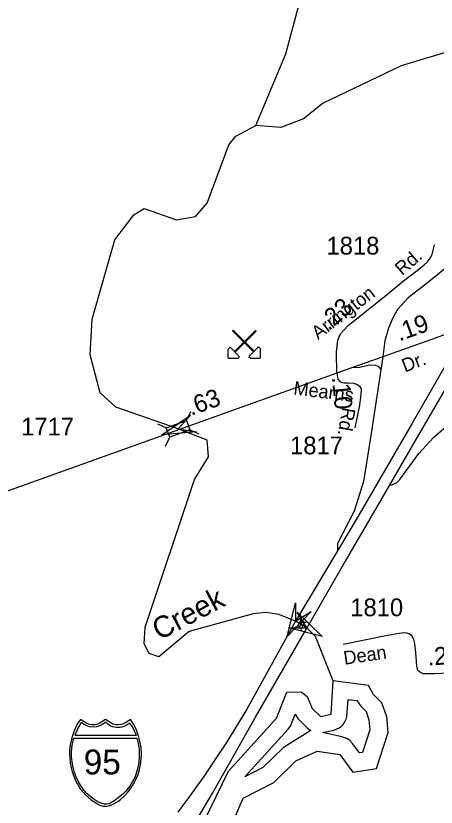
# Model space of a CAD drawing. Extents: x 2220236 to 2384410, y 720751 to 894131.
# Drawn here: x 2314927 to 2317882, y 782328 to 787885 of the extents above; entities that cross this region are included whole.
import ezdxf

# ---------------------------------------------------------------- set-up
doc = ezdxf.new("R2010")
doc.units = 0
for name, color, linetype in [('Exist Geographical Pit Clay CELL', 7, 'Continuous'), ('Exist Hydrographic Buffer Line', 7, 'Continuous'), ('Exist Hydrographic Creek Single Shore', 7, 'Continuous'), ('Exist Hydrographic Creek Single Shore Label', 7, 'Continuous'), ('Exist Hydrographic Lake Shore', 7, 'Continuous'), ('Exist Hydrographic Misc Water Feature', 7, 'Continuous'), ('Exist Road Primary Interstate Divided Center Attributed', 7, 'Continuous'), ('Exist Road Primary Interstate Ramp 1 Lane Attributed', 7, 'Continuous'), ('Exist Road Primary Interstate Shield CELL', 7, 'Continuous'), ('Exist Road Primary Interstate Shield Number Label', 7, 'Continuous'), ('Exist Road Primary Interstate Structure Standard Bridge CELL', 7, 'Continuous'), ('Exist Road Primary US Service Attributed', 7, 'Continuous'), ('Exist Road Secondary Mileage Hundredths English Label', 7, 'Continuous'), ('Exist Road Secondary Structure Standard Bridge Attributed CELL', 7, 'Continuous'), ('Exist Road Secondary Structure Standard Bridge CELL', 7, 'Continuous'), ('Exist Road Secondary Type 51 Attributed', 7, 'Continuous'), ('Exist Road Secondary Type 51 Label', 7, 'Continuous'), ('Exist Road Secondary Type 51 Number Label', 7, 'Continuous')]:
    doc.layers.add(name, color=color, linetype=linetype)

msp = doc.modelspace()

# ---------------------------------------------------------------- linework, layer by layer
at = {"layer": 'Exist Geographical Pit Clay CELL'}
for points in [[(2316597.8, 785524.9), (2316602.6, 785529.7), (2316455.3, 785677), (2316450.5, 785672.2)], [(2316469.6, 785522.4), (2316464.8, 785527.2), (2316612.1, 785674.5), (2316616.9, 785669.7)], [(2316420, 785483), (2316420, 785545.1), (2316433.5, 785558.6), (2316501, 785491.1), (2316487.5, 785477.6), (2316425.4, 785477.6)], [(2316647.4, 785485.4), (2316647.4, 785547.5), (2316633.9, 785561), (2316566.4, 785493.5), (2316579.9, 785480), (2316642, 785480)]]:
    msp.add_lwpolyline(points, close=True, dxfattribs=at)
at = {"layer": 'Exist Hydrographic Buffer Line'}
for points in [[(2317343.6, 782708.6), (2317294, 782774.8), (2317275.1, 782794.8), (2317257.9, 782806.8), (2317238.8, 782815.6), (2317218.7, 782821), (2317082.6, 782851.5), (2317162.2, 782868.6), (2317196.8, 782882), (2317214.2, 782894), (2317229, 782908.8), (2317240.9, 782925.9), (2317249.7, 782944.8), (2317255.2, 782965.1), (2317262.8, 783083.9), (2317323.9, 783076), (2317351.6, 783036.2), (2317389.6, 782999.8), (2317409.7, 782940.7), (2317416.2, 782871.2), (2317365.2, 782712), (2317343.6, 782708.6)], [(2316537.4, 782540.9), (2316842.7, 782876.4), (2316857.9, 782897.2), (2316892.1, 782981.1), (2316911, 782949.3), (2316978.6, 782883.2), (2317001.8, 782865.8), (2316839.8, 782766.5), (2316806.4, 782743.8), (2316663.5, 782605.4), (2316537.4, 782540.9)]]:
    msp.add_lwpolyline(points, dxfattribs=at)
at = {"layer": 'Exist Hydrographic Creek Single Shore'}
for points in [[(2316615.7, 787114.3), (2316826.7, 787618.5), (2316922.7, 787976.9)], [(2317157.7, 783214.5), (2317033.1, 783525.9), (2316974, 783586), (2316932.3, 783611.5), (2316894.3, 783633.8), (2316776.6, 783681.7), (2316688.1, 783693.9), (2316596.5, 783685.8), (2316145.7, 783560.5), (2315931.7, 783384.4), (2315864.6, 783407.9), (2315830.6, 783475.5), (2315837.7, 783590.6), (2316184.7, 784628.7), (2316282.7, 784787), (2316272.7, 784904.8), (2316069.5, 784983.8), (2315629.6, 785137.8), (2315519.7, 785238.2), (2315450.6, 785504.5), (2315464.8, 785754.6), (2315624.7, 786312.5), (2315756.7, 786488.4), (2315830.6, 786530.9), (2316056.7, 786451.5), (2316189.6, 786476.7), (2316271.6, 786568.6), (2316425.6, 786978.5), (2316474.6, 787039.6), (2316615.7, 787114.3)]]:
    msp.add_lwpolyline(points, dxfattribs=at)
at = {"layer": 'Exist Hydrographic Lake Shore'}
for points in [[(2316364.7, 779440.9), (2316363.7, 779598.3), (2316537.6, 780376.7), (2316619.6, 780501.5), (2316736.7, 780519.3), (2316760.7, 780586), (2316724.6, 780893), (2316480.6, 781116), (2316404.7, 781208.1), (2316376.6, 781456.4), (2316457.6, 781699.3), (2316280.7, 781829.9), (2316238.6, 781897.1), (2316227.8, 782129.7), (2316251.8, 782229.1), (2316422.8, 782580.7), (2316760.7, 782952.2), (2316833.7, 783135.7), (2316933.8, 783136.5), (2316975.8, 783105.4), (2317009.6, 783021.5), (2317068.7, 782964.8), (2317143.7, 782981), (2317157.7, 783214.5)], [(2316427.7, 782164.1), (2316524.7, 782391.2), (2316740.6, 782501.7), (2316896.6, 782652.5), (2317045.7, 782721.1), (2317204.6, 782697.9), (2317297.7, 782573.7), (2317463.6, 782600.2), (2317544.6, 782852.9), (2317534.8, 782960.9), (2317500.7, 783061.2), (2317441.7, 783117.8), (2317407.6, 783182.1), (2317157.7, 783214.5)]]:
    msp.add_lwpolyline(points, dxfattribs=at)
at = {"layer": 'Exist Hydrographic Misc Water Feature'}
msp.add_lwpolyline([(2321080.8, 787129.2), (2320564.9, 787006.4), (2320123.8, 786962.2), (2319925.7, 786858.9), (2319717.8, 786830.7), (2319583.7, 786887.6), (2319396.7, 787178.6), (2319379.9, 787276.4), (2319277.7, 787475.7), (2319041.7, 787748.3), (2318848.8, 787829), (2318615.8, 787829.3), (2317635.7, 787533.4), (2317088.8, 787271.5), (2316948.7, 787160.7), (2316790.6, 787101.7), (2316615.7, 787114.3)], dxfattribs=at)
at = {"layer": 'Exist Road Primary Interstate Divided Center Attributed'}
for points in [[(2317554.7, 784587), (2317735.2, 784897.4), (2318131.4, 785576.4), (2318235.6, 785754.9)], [(2318109.9, 785708.2), (2318003.5, 785527.8), (2317954.2, 785444.3), (2317710.9, 785019.2), (2317340.2, 784382.4), (2317275.7, 784274.1), (2317187.7, 784127.5)], [(2316971.3, 783579.3), (2317222.3, 784015.3), (2317441.6, 784392.4), (2317554.7, 784587)], [(2317187.7, 784127.5), (2316894.3, 783633.8)], [(2316894.3, 783633.8), (2316550.3, 783017), (2316408, 782782.9), (2316336.9, 782674.3), (2316254.5, 782550.7), (2316164.7, 782425.2), (2316065.5, 782292.2)], [(2316217.1, 782267.9), (2316310.7, 782425.2), (2316428.6, 782636.8), (2316612.1, 782959), (2316971.3, 783579.3)]]:
    msp.add_lwpolyline(points, dxfattribs=at)
at = {"layer": 'Exist Road Primary Interstate Ramp 1 Lane Attributed'}
for points in [[(2318653.5, 786811.6), (2318612.5, 786797.6), (2318507.3, 786661.7), (2318413.4, 786532.8), (2318328.4, 786437.6), (2318207.3, 786325), (2318057.3, 786201), (2317820.9, 786010.6), (2317684.9, 785905.5), (2317609.6, 785821.6), (2317577, 785763.8), (2317546.7, 785691.6), (2317522.2, 785603.6), (2317507.8, 785489)], [(2317554.7, 784587), (2317601.4, 784601.9), (2317626.7, 784629), (2317760.1, 784810.7), (2317863.1, 784923), (2318100.3, 785129), (2318392.9, 785336.8), (2318610, 785501.1), (2318707.1, 785601.7), (2318756.2, 785672.9), (2318785, 785732), (2318819.6, 785818.6), (2318838.4, 785871.9), (2318848.5, 785942.6)], [(2317507.8, 785489), (2317494, 785399.1)], [(2317301.4, 785416.7), (2317339.6, 785415.7), (2317363.2, 785421.8), (2317415.3, 785433), (2317455.7, 785431.8), (2317477.6, 785422.1), (2317494, 785399.1)], [(2317494, 785399.1), (2317425, 784951.5), (2317371.1, 784615.2), (2317305.7, 784407.5), (2317187.7, 784178.9), (2317187.7, 784127.5)]]:
    msp.add_lwpolyline(points, dxfattribs=at)
at = {"layer": 'Exist Road Primary Interstate Shield CELL'}
for points in [[(2315557.9, 782333.6), (2315567.4, 782334.5), (2315580.1, 782337), (2315592.5, 782341), (2315606.6, 782347.3), (2315627.5, 782358.8), (2315644.2, 782368.6), (2315663.6, 782381.6), (2315689.7, 782405.3), (2315715.7, 782432.7), (2315738.7, 782463.8), (2315757, 782492.8), (2315773, 782525.9), (2315786.5, 782556.9), (2315797.1, 782592.2), (2315804.2, 782626.4), (2315807.8, 782662.1), (2315810.2, 782701.7), (2315807.5, 782746.2), (2315799.7, 782791.8), (2315792.4, 782820.2), (2315781.4, 782854.1), (2315772.4, 782875.8), (2315751.6, 782914.2), (2315732.8, 782943.8), (2315705.6, 782924.6), (2315687.8, 782915.2), (2315677, 782910.3), (2315665.9, 782908.1), (2315645.4, 782905.7), (2315632.5, 782906.2), (2315620.5, 782908.9), (2315610.4, 782911.1), (2315602.2, 782915.2), (2315557.9, 782943.8), (2315513.6, 782915.2), (2315504.4, 782910.9), (2315494.9, 782908.9), (2315485.7, 782906.4), (2315470.6, 782905.7), (2315459, 782906), (2315447.1, 782908.1), (2315437.8, 782910.1), (2315427.2, 782915.2), (2315382.1, 782943.8), (2315364.4, 782918.1), (2315349.9, 782892.7), (2315334.6, 782856.8), (2315325, 782828.9), (2315318.2, 782806), (2315309.9, 782764.1), (2315305.6, 782727.5), (2315304.8, 782701.7), (2315309.5, 782637.2), (2315316.6, 782602.8), (2315323.8, 782575), (2315347.7, 782515), (2315365.6, 782481.4), (2315381, 782457.2), (2315402.6, 782430.1), (2315414.3, 782417.1), (2315459.1, 782377.9), (2315489, 782357.5), (2315512.9, 782344.6), (2315524.2, 782340.3), (2315541.7, 782335.4)], [(2315387.5, 782923.1), (2315376.5, 782906.1), (2315363.8, 782883.3), (2315353.7, 782859.6), (2315343.3, 782833.5), (2315774.9, 782833.3), (2315764.8, 782855.7), (2315754.1, 782878.3), (2315742.8, 782898.8), (2315729.1, 782918.7), (2315704.9, 782903.5), (2315687.3, 782895.2), (2315673.1, 782890.3), (2315661.1, 782887.6), (2315642.5, 782886.1), (2315634.2, 782886.6), (2315608.3, 782892.5), (2315590.7, 782899.6), (2315574, 782910.8), (2315560.5, 782923.5), (2315526.3, 782902.8), (2315511.2, 782896.1), (2315493.7, 782891.7), (2315474.6, 782889.3), (2315445.2, 782892.5), (2315422.1, 782900.4), (2315402.2, 782910.8)], [(2315777.4, 782812), (2315782.1, 782799.8), (2315788.4, 782772.8), (2315791.8, 782751.9), (2315795.2, 782728), (2315794, 782686.8), (2315792, 782644.2), (2315788.1, 782619), (2315782.9, 782596.1), (2315775.7, 782570.6), (2315764.2, 782536.8), (2315748.3, 782508.1), (2315728.4, 782476.3), (2315706.9, 782448.5), (2315697.6, 782436.9), (2315679.9, 782418.2), (2315647.6, 782392.4), (2315624.1, 782374.8), (2315595.9, 782358.1), (2315581.6, 782351.8), (2315565, 782348.3), (2315551.3, 782349.2), (2315534.6, 782353.7), (2315521.2, 782357.3), (2315491.8, 782373.3), (2315467.9, 782389.2), (2315428.1, 782421.8), (2315406.7, 782446.9), (2315386.6, 782476.3), (2315368.8, 782506.4), (2315349.7, 782546.1), (2315336.2, 782586), (2315326.4, 782629.1), (2315319.8, 782681.7), (2315319.1, 782713.8), (2315321.1, 782744.6), (2315324, 782760.8), (2315327.9, 782780.8), (2315335.8, 782811.8)]]:
    msp.add_lwpolyline(points, close=True, dxfattribs=at)
at = {"layer": 'Exist Road Primary Interstate Structure Standard Bridge CELL'}
for p, q in [((2316920.8, 783590.7), (2316943.9, 783632.2)), ((2316930.1, 783639.9), (2316928, 783658.6)), ((2316957.4, 783624.6), (2316974.5, 783632.7)), ((2316889.9, 783590.4), (2316906.9, 783598.4)), ((2316936.7, 783564.3), (2316934.6, 783583))]:
    msp.add_line(p, q, dxfattribs=at)
msp.add_lwpolyline([(2316934.6, 783583), (2316957.7, 783624.5), (2316930.1, 783639.9), (2316906.9, 783598.4)], close=True, dxfattribs=at)
at = {"layer": 'Exist Road Primary US Service Attributed'}
for points in [[(2317183.7, 785375.4), (2317182.3, 785521.8), (2317190.9, 785606.9), (2317199.6, 785631.5), (2317209.7, 785651.7), (2317229.9, 785676.2), (2317263, 785710.8), (2317335.1, 785767.1), (2317528.3, 785921.4), (2317653.7, 786023.8), (2317758.9, 786103.2), (2317797.8, 786136.4), (2317820.9, 786156.5), (2317841.1, 786182.5), (2317854.1, 786208.5), (2317869.9, 786276.3)], [(2317183.7, 785375.4), (2317191.5, 785333.7), (2317207.4, 785313.5), (2317233.3, 785307.8), (2317265, 785307.8), (2317301.1, 785304.9), (2317328.5, 785294.8), (2317342.9, 785283.2), (2317354.4, 785265.9), (2317352.4, 785225.7), (2317342.9, 785150.5), (2317311.2, 784991.9)]]:
    msp.add_lwpolyline(points, dxfattribs=at)
at = {"layer": 'Exist Road Secondary Structure Standard Bridge Attributed CELL'}
for points in [[(2316197.7, 784962.5), (2315954.6, 784942.8), (2316155.2, 785081.4), (2316069.5, 784983.8)], [(2317004.7, 783702.3), (2316835, 783527.3), (2316894.5, 783763.8), (2316894.3, 783633.8)], [(2316905.6, 783696.5), (2317080.5, 783526.6), (2316844.1, 783586.2), (2316974, 783586)]]:
    msp.add_lwpolyline(points, close=True, dxfattribs=at)
at = {"layer": 'Exist Road Secondary Structure Standard Bridge CELL'}
for p, q in [((2316127.4, 785042.9), (2316156.6, 785105.4)), ((2315922.8, 785020.7), (2315985.3, 784991.6)), ((2316151, 784978.1), (2316213.6, 784948.9)), ((2315980.3, 784862.7), (2316009.5, 784925.2))]:
    msp.add_line(p, q, dxfattribs=at)
msp.add_lwpolyline([(2315985.3, 784991.6), (2316127.3, 785043.2), (2316151.5, 784976.9), (2316009.5, 784925.2)], close=True, dxfattribs=at)
at = {"layer": 'Exist Road Secondary Type 51 Attributed'}
for points in [[(2318109.9, 785708.2), (2318023.5, 785675.8), (2318009.2, 785670.6), (2317881.2, 785624.6), (2317507.8, 785489)], [(2317507.8, 785489), (2317301.4, 785416.7)], [(2317301.4, 785416.7), (2317183.7, 785375.4)], [(2317183.7, 785375.4), (2316070, 784977.3)], [(2316070, 784977.3), (2314035.9, 784249.9)], [(2318252.1, 783278.9), (2318039.7, 783271.2), (2317975, 783267.9), (2317919.3, 783266.6), (2317867.5, 783263.4), (2317845.5, 783263.4), (2317822.2, 783264.7), (2317791.1, 783263.4), (2317771.7, 783272.5), (2317753.5, 783286.7), (2317745.8, 783317.8), (2317744.5, 783351.5), (2317741.9, 783383.9), (2317736.7, 783434.4), (2317731.5, 783476.5), (2317725, 783504.4), (2317710.8, 783530.3), (2317697.8, 783542), (2317677.1, 783548.5), (2317653.8, 783552.3), (2317607.2, 783545.9), (2317581.3, 783540.7), (2317539.9, 783532.9), (2317229.1, 783469.4)]]:
    msp.add_lwpolyline(points, dxfattribs=at)

# ---------------------------------------------------------------- texts
at = {"layer": 'Exist Hydrographic Creek Single Shore Label'}
msp.add_text('Creek', height=150, rotation=27.6816, dxfattribs=at).set_placement((2315935.8, 783496.7))
at = {"layer": 'Exist Road Primary Interstate Shield Number Label'}
msp.add_text('95', height=175, dxfattribs=at).set_placement((2315405, 782557.4))
at = {"layer": 'Exist Road Secondary Mileage Hundredths English Label'}
for s, rotation, p in [('.23', 41.0169, (2317127.3, 785668.7)), ('.19', 19.9594, (2317623.5, 785597.5)), ('.10', 275.4792, (2317149.2, 785346.3)), ('.63', 19.6705, (2316158.8, 785075.4)), ('.24', 3.7778, (2317825.1, 783321.6))]:
    msp.add_text(s, height=125, rotation=rotation, dxfattribs=at).set_placement(p)
at = {"layer": 'Exist Road Secondary Type 51 Label'}
for s, rotation, p in [('Rd.', 40.8209, (2317643, 786056.8)), ('Arrington', 37.2561, (2317051.7, 785607.4)), ('Dr.', 20.7651, (2317662.5, 785379.7)), ('Mearns', 353.0214, (2316876, 785225.2)), ('Rd.', 260.3415, (2317223, 785139)), ('Dean', 8.3654, (2317238.1, 783327.4))]:
    msp.add_text(s, height=95, rotation=rotation, dxfattribs=at).set_placement(p)
at = {"layer": 'Exist Road Secondary Type 51 Number Label'}
for s, p in [('1818', (2317111.4, 786208.4)), ('1717', (2314964.8, 784937.9)), ('1817', (2316855.2, 784805.6)), ('1810', (2317278.5, 783668.4))]:
    msp.add_text(s, height=125, dxfattribs=at).set_placement(p)

doc.saveas('drawing.dxf')
